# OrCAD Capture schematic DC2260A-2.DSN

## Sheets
1 1) TITLE: title: isoSPI 12-CELL BATTERY-STACK MONITOR; rev: 1; company: TM
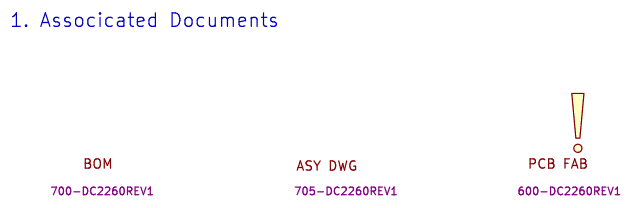
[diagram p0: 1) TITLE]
2 LTC6811IG-2: size Custom; rev: 2
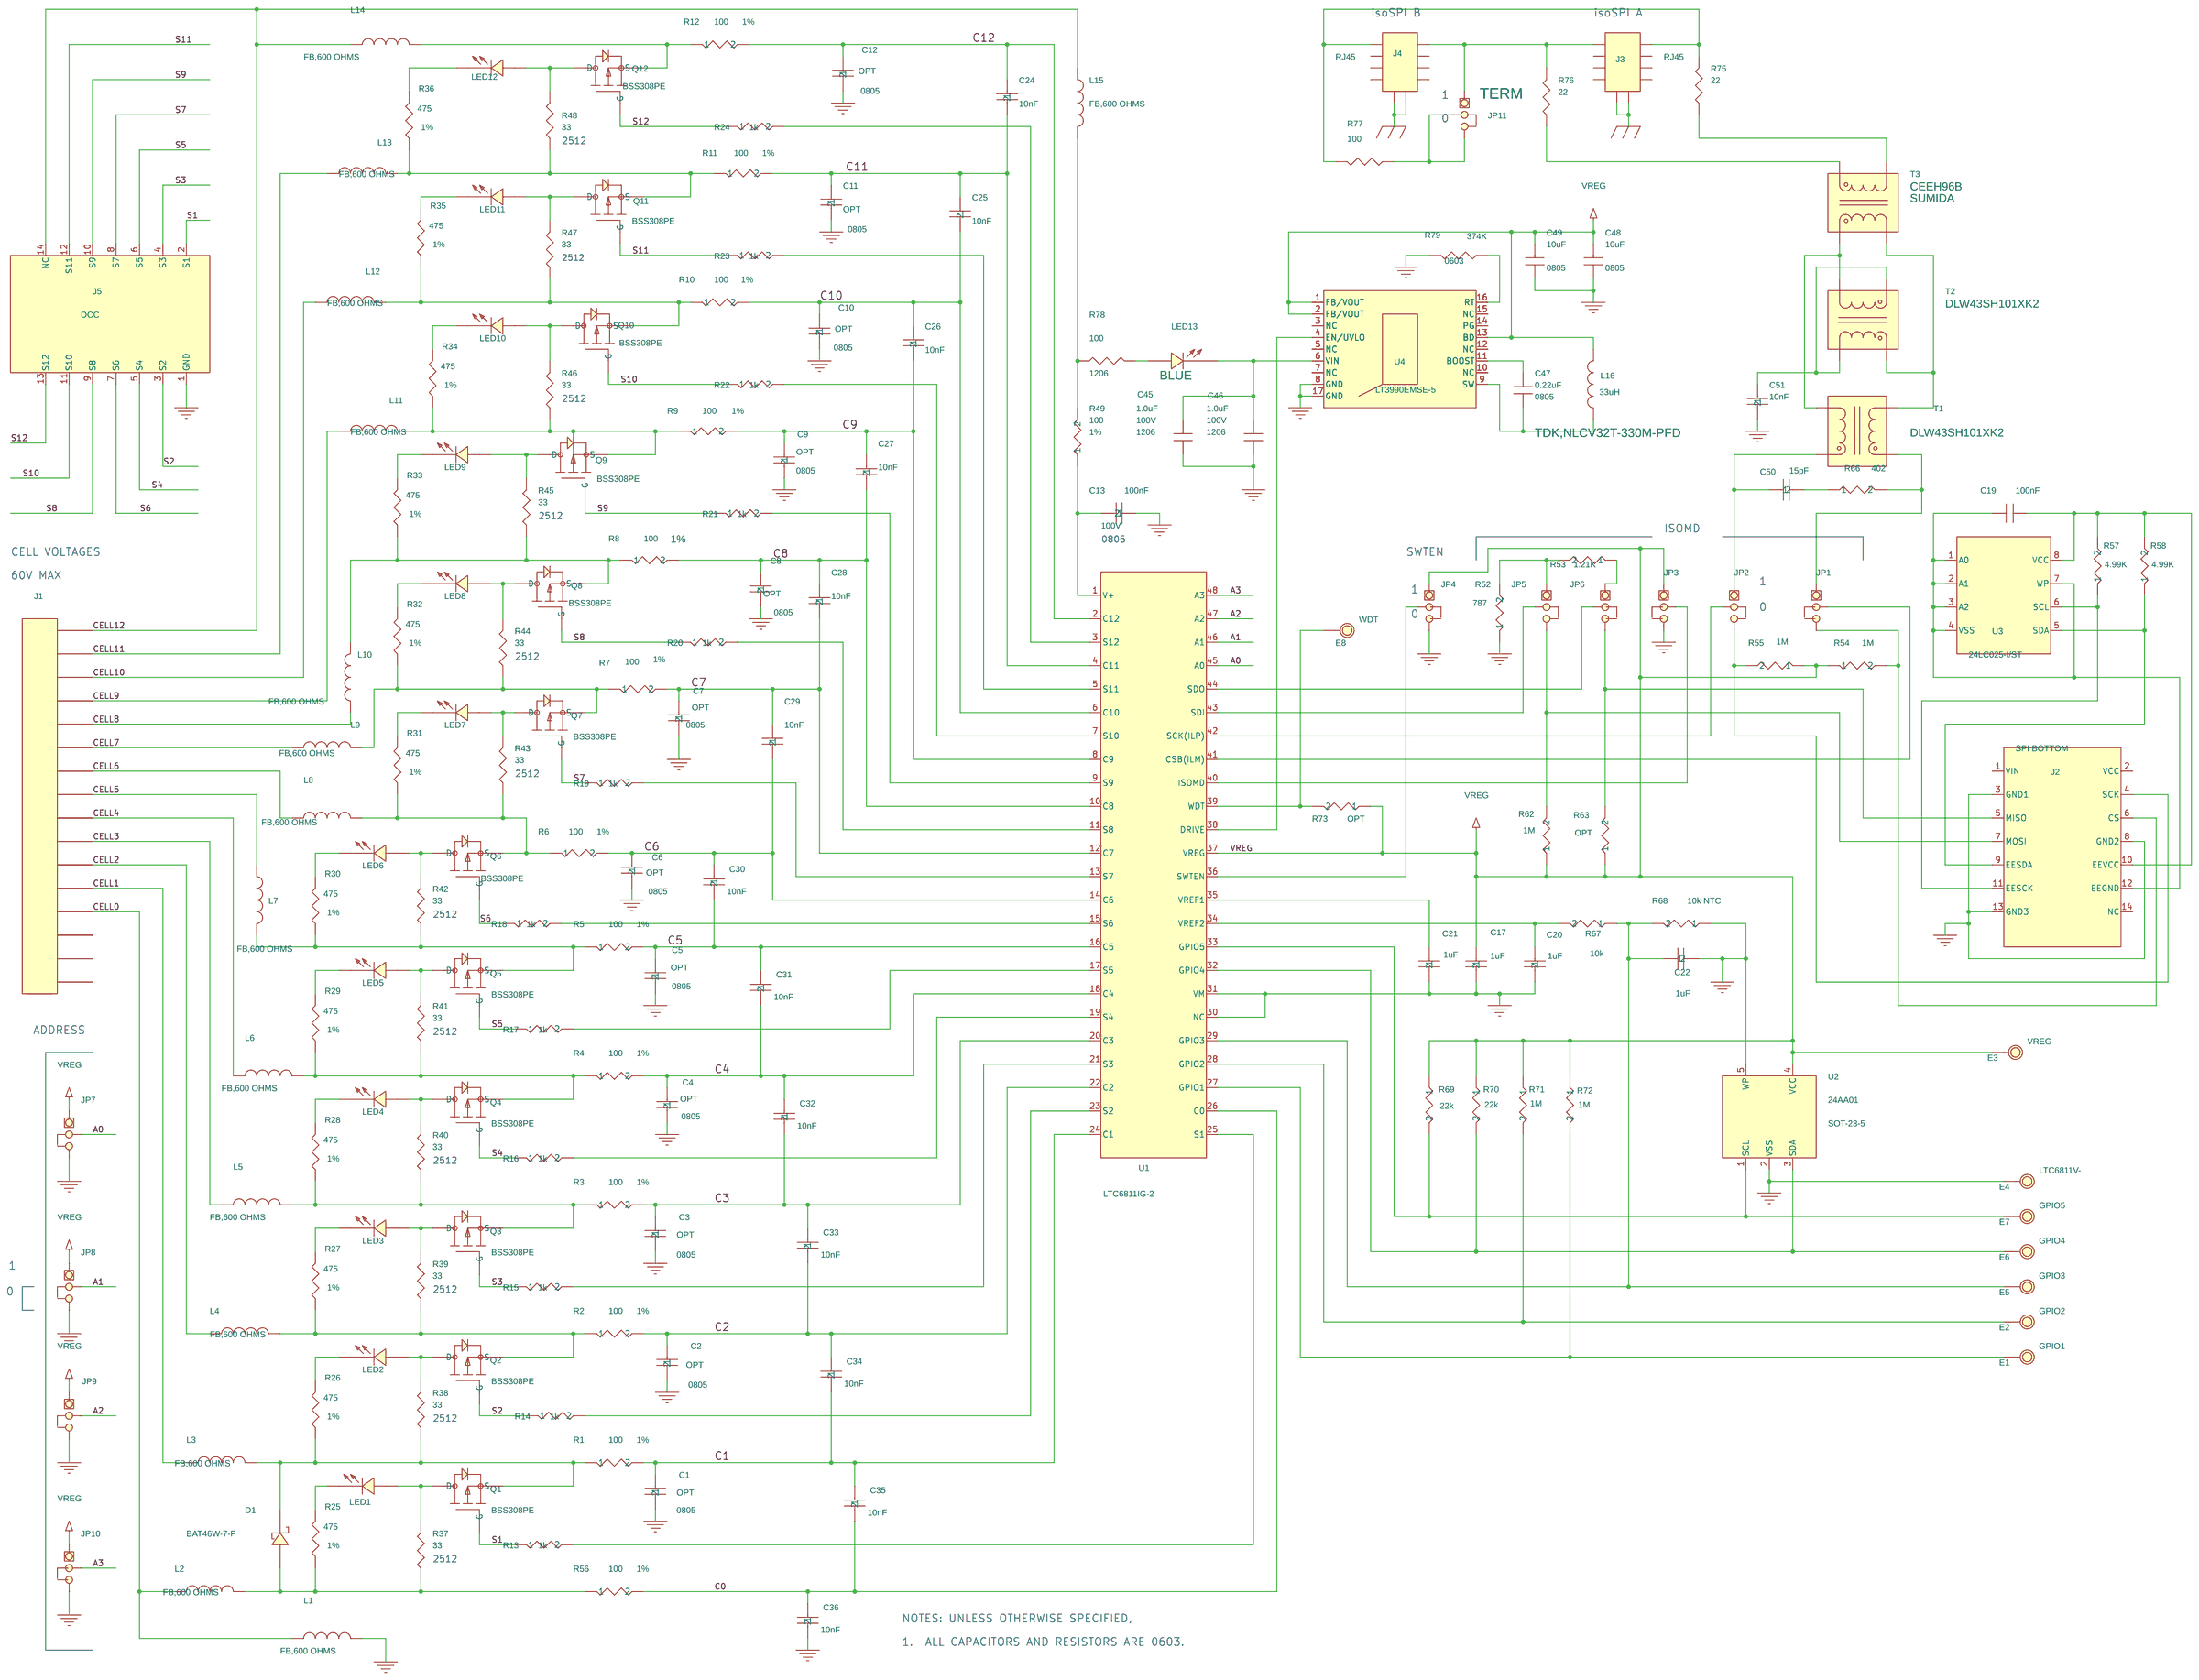
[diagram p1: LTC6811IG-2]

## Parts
sheet 1) TITLE
WARNINGL1  CALLOUT_BOM
WARNINGL2  CALLOUT_ASSY_DWG
WARNINGL3  CALLOUT_PCB_FAB
sheet LTC6811IG-2
C1  OPT  [0805]
C2  OPT  [0805]
C3  OPT  [0805]
C4  OPT  [0805]
C5  OPT  [0805]
C6  OPT  [0805]
C7  OPT  [0805]
C8  OPT  [0805]
C9  OPT  [0805]
C10  OPT  [0805]
C11  OPT  [0805]
C12  OPT  [0805]
C13  100nF  [C0805]
C17  1uF  [C0603]
C19  100nF  [C0603]
C20  1uF  [C0603]
C21  1uF  [C0603]
C22  1uF  [C0603]
C24  10nF  [C0603]
C25  10nF  [C0603]
C26  10nF  [C0603]
C27  10nF  [C0603]
C28  10nF  [C0603]
C29  10nF  [C0603]
C30  10nF  [C0603]
C31  10nF  [C0603]
C32  10nF  [C0603]
C33  10nF  [C0603]
C34  10nF  [C0603]
C35  10nF  [C0603]
C36  10nF  [C0603]
C45  1.0uF  [1206]
C46  1.0uF  [1206]
C47  0.22uF  [0805]
C48  10uF  [0805]
C49  10uF  [0805]
C50  15pF  [C0603]
C51  10nF  [C0603]
D1  BAT46W-7-F  [SOD123]
E1  GPIO1  [MILLMAX-2308-2]
E2  GPIO2  [MILLMAX-2308-2]
E3  VREG  [MILLMAX-2308-2]
E4  LTC6811V-  [MILLMAX-2308-2]
E5  GPIO3  [MILLMAX-2308-2]
E6  GPIO4  [MILLMAX-2308-2]
E7  GPIO5  [MILLMAX-2308-2]
E8  WDT  [MILLMAX-2308-2]
J1  HEADER 16  [CONN\WDMLLR\176168200]
J2  SPI BOTTOM  [HD2X7-079-MOLEX]
J3  RJ45  [RJ45]
J4  RJ45  [RJ45]
J5  DCC  [HD2X7-079-MOLEX]
JP1  JMP1X3  [JUMPER3\2MM]
JP2  JMP1X3  [JUMPER3\2MM]
JP3  JMP1X3  [JUMPER3\2MM]
JP4  JMP1X3  [JUMPER3\2MM]
JP5  JMP1X3  [JUMPER3\2MM]
JP6  JMP1X3  [JUMPER3\2MM]
JP7  JMP1X3  [JUMPER3\2MM]
JP8  JMP1X3  [JUMPER3\2MM]
JP9  JMP1X3  [JUMPER3\2MM]
JP10  JMP1X3  [JUMPER3\2MM]
JP11  JMP1X3  [JUMPER3\2MM]
L1  FB,600 OHMS  [1206]
L2  FB,600 OHMS  [1206]
L3  FB,600 OHMS  [1206]
L4  FB,600 OHMS  [1206]
L5  FB,600 OHMS  [1206]
L6  FB,600 OHMS  [1206]
L7  FB,600 OHMS  [1206]
L8  FB,600 OHMS  [1206]
L9  FB,600 OHMS  [1206]
L10  FB,600 OHMS  [1206]
L11  FB,600 OHMS  [1206]
L12  FB,600 OHMS  [1206]
L13  FB,600 OHMS  [1206]
L14  FB,600 OHMS  [1206]
L15  FB,600 OHMS  [1206]
L16  33uH  [IND-NLCV]
LED1  LED  [LED\LTST-C190KGKT]
LED2  LED  [LED\LTST-C190KGKT]
LED3  LED  [LED\LTST-C190KGKT]
LED4  LED  [LED\LTST-C190KGKT]
LED5  LED  [LED\LTST-C190KGKT]
LED6  LED  [LED\LTST-C190KGKT]
LED7  LED  [LED\LTST-C190KGKT]
LED8  LED  [LED\LTST-C190KGKT]
LED9  LED  [LED\LTST-C190KGKT]
LED10  LED  [LED\LTST-C190KGKT]
LED11  LED  [LED\LTST-C190KGKT]
LED12  LED  [LED\LTST-C190KGKT]
LED13  BLUE  [LED\LTST-C190KGKT]
P1  HEADER 16/SM
Q1  BSS308PE  [SOT23]
Q2  BSS308PE  [SOT23]
Q3  BSS308PE  [SOT23]
Q4  BSS308PE  [SOT23]
Q5  BSS308PE  [SOT23]
Q6  BSS308PE  [SOT23]
Q7  BSS308PE  [SOT23]
Q8  BSS308PE  [SOT23]
Q9  BSS308PE  [SOT23]
Q10  BSS308PE  [SOT23]
Q11  BSS308PE  [SOT23]
Q12  BSS308PE  [SOT23]
R1  100  [R0603]
R2  100  [R0603]
R3  100  [R0603]
R4  100  [R0603]
R5  100  [R0603]
R6  100  [R0603]
R7  100  [R0603]
R8  100  [R0603]
R9  100  [R0603]
R10  100  [R0603]
R11  100  [R0603]
R12  100  [R0603]
R13  1k  [R0603]
R14  1k  [R0603]
R15  1k  [R0603]
R16  1k  [R0603]
R17  1k  [R0603]
R18  1k  [R0603]
R19  1k  [R0603]
R20  1k  [R0603]
R21  1k  [R0603]
R22  1k  [R0603]
R23  1k  [R0603]
R24  1k  [R0603]
R25  475  [R0603]
R26  475  [R0603]
R27  475  [R0603]
R28  475  [R0603]
R29  475  [R0603]
R30  475  [R0603]
R31  475  [R0603]
R32  475  [R0603]
R33  475  [R0603]
R34  475  [R0603]
R35  475  [R0603]
R36  475  [R0603]
R37  33  [2512]
R38  33  [2512]
R39  33  [2512]
R40  33  [2512]
R41  33  [2512]
R42  33  [2512]
R43  33  [2512]
R44  33  [2512]
R45  33  [2512]
R46  33  [2512]
R47  33  [2512]
R48  33  [2512]
R49  100  [R0603]
R52  787  [R0603]
R53  1.21K  [R0603]
R54  1M  [0603]
R55  1M  [0603]
R56  100  [R0603]
R57  4.99K  [R0603]
R58  4.99K  [R0603]
R62  1M  [0603]
R63  OPT  [0603]
R66  402  [R0603]
R67  10k  [0603]
R68  10k NTC  [0603]
R69  22k  [0603]
R70  22k  [0603]
R71  1M  [0603]
R72  1M  [0603]
R73  OPT  [0603]
R75  22  [R0603]
R76  22  [R0603]
R77  100  [R0603]
R78  100  [1206]
R79  374K  [0603]
T1  DLW43SH101XK2  [TRANS-DLW43S]
T2  DLW43SH101XK2  [TRANS-DLW43S]
T3  CEEH96B  [TRANS-CEEH96B]
U1  LTC6811IG-2  [LTC-SSOP48-5.3MM]
U2  24AA01  [SOT-23-5]
U3  24LC025-I/ST  [ST-4.4MMTSSOP]
U4  LT3990EMSE-5  [MSE-16PIN]
XJP8  2mm Ctrs.
XJP9  2mm Ctrs.
XJP10  2mm Ctrs.
XJP11  2mm Ctrs.
XJP12  2mm Ctrs.
XJP13  2mm Ctrs.
XJP14  2mm Ctrs.
XJP15  2mm Ctrs.
XJP16  2mm Ctrs.
XJP17  2mm Ctrs.
XJP18  2mm Ctrs.

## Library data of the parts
WARNINGL1 = CALLOUT_BOM: Part Number: 700-DC2260REV1
WARNINGL2 = CALLOUT_ASSY_DWG: Part Number: 705-DC2260REV1
WARNINGL3 = CALLOUT_PCB_FAB: Part Number: 600-DC2260REV1
C1 = CAP_NP_1_16: CAP, 0603 100nF 10% 25V X7R; Part Number: MURATA GCM188R71E104KA57D
C2 = CAP_NP_1_15: CAP, 0603 100nF 10% 25V X7R; Part Number: MURATA GCM188R71E104KA57D
C3 = CAP_NP_1_13: CAP, 0603 100nF 10% 25V X7R; Part Number: MURATA GCM188R71E104KA57D
C4 = CAP_NP_1_10: CAP, 0603 100nF 10% 25V X7R; Part Number: MURATA GCM188R71E104KA57D
C5 = CAP_NP_1_24: CAP, 0603 100nF 10% 25V X7R; Part Number: MURATA GCM188R71E104KA57D
C6 = CAP_NP_1_29: CAP, 0603 100nF 10% 25V X7R; Part Number: MURATA GCM188R71E104KA57D
C7 = CAP_NP_1_6: CAP, 0603 100nF 10% 25V X7R; Part Number: MURATA GCM188R71E104KA57D
C8 = CAP_NP_1_3: CAP, 0603 100nF 10% 25V X7R; Part Number: MURATA GCM188R71E104KA57D
C9 = CAP_NP_1_27: CAP, 0603 100nF 10% 25V X7R; Part Number: MURATA GCM188R71E104KA57D
C10 = CAP_NP_1_28: CAP, 0603 100nF 10% 25V X7R; Part Number: MURATA GCM188R71E104KA57D
C11 = CAP_NP_1_8: CAP, 0603 100nF 10% 25V X7R; Part Number: MURATA GCM188R71E104KA57D
C12 = CAP_NP_1_9: CAP, 0603 100nF 10% 25V X7R; Part Number: MURATA GCM188R71E104KA57D
C13 = CAP_NP_1_11: CAP, 0805 100nF 20% 100V X7R; Part Number: MURATA GCM21BR72A104KA37; voltage: 100V
C17 = CAP_NP_1_30: CAP, 0603 100nF 10% 25V X7R; Part Number: MURATA GCM188R71E104KA57D
C19 = CAP0603: CAP, 0603 100nF 10% 25V X7R; Part Number: MURATA GCM188R71E104KA57D; Voltage: 25V
C20 = CAP_NP_1_21: CAP, 0603 100nF 10% 25V X7R; Part Number: MURATA GCM188R71E104KA57D
C21 = CAP_NP_1_18: CAP, 0603 100nF 10% 25V X7R; Part Number: MURATA GCM188R71E104KA57D
C22 = CAP_NP_1_22: CAP, 0603 100nF 10% 25V X7R; Part Number: MURATA GCM188R71E104KA57D
C24 = CAP_NP_1_26: CAP, 0603 100nF 10% 25V X7R; Part Number: MURATA GCM188R71E104KA57D
C25 = CAP_NP_1_23: CAP, 0603 100nF 10% 25V X7R; Part Number: MURATA GCM188R71E104KA57D
C26 = CAP_NP_1_17: CAP, 0603 100nF 10% 25V X7R; Part Number: MURATA GCM188R71E104KA57D
C27 = CAP_NP_1_12: CAP, 0603 100nF 10% 25V X7R; Part Number: MURATA GCM188R71E104KA57D
C28 = CAP_NP_1_2: CAP, 0603 100nF 10% 25V X7R; Part Number: MURATA GCM188R71E104KA57D
C29 = CAP_NP_1_5: CAP, 0603 100nF 10% 25V X7R; Part Number: MURATA GCM188R71E104KA57D
C30 = CAP_NP_1_4: CAP, 0603 100nF 10% 25V X7R; Part Number: MURATA GCM188R71E104KA57D
C31 = CAP_NP_1_31: CAP, 0603 100nF 10% 25V X7R; Part Number: MURATA GCM188R71E104KA57D
C32 = CAP_NP_1_19: CAP, 0603 100nF 10% 25V X7R; Part Number: MURATA GCM188R71E104KA57D
C33 = CAP_NP_1_20: CAP, 0603 100nF 10% 25V X7R; Part Number: MURATA GCM188R71E104KA57D
C34 = CAP_NP_1_25: CAP, 0603 100nF 10% 25V X7R; Part Number: MURATA GCM188R71E104KA57D
C35 = CAP_NP_1: CAP, 0603 100nF 10% 25V X7R; Part Number: MURATA GCM188R71E104KA57D
C36 = CAP_NP_1_14: CAP, 0603 100nF 10% 25V X7R; Part Number: MURATA GCM188R71E104KA57D
C45 C46 = 1.0uF_25V_10%_X7R_0805: CAP., 1uF, X7R, 100V, 10%, 0805; Voltage: 100V
C47 = 0.22uF_25V_10%_X7R_0805
C48 C49 = 10uF_10V_20%_X5R_0805
C50 = CAP_NP_1_7: CAP, 0603 100nF 10% 25V X7R; Part Number: MURATA GCM188R71E104KA57D
C51 = CAP_NP_1_1: CAP, 0603 100nF 10% 25V X7R; Part Number: MURATA GCM188R71E104KA57D
D1 = DIODE_SCHOTTKY
E1-E8 = CON_KEY_575-4: 5th Part Field: 3V to 3.6V
J1 = HEADER_16_1: HEADER, 1X16 3.5mm, HORIZ.; Part Number: WEIDMULLER 1761682001
J2 = HEADER_7X2_8
J3 = HEADER_16_8
J4 = HEADER_16_7
J5 = HEADER_7X2_9
JP1 = JMP1X3_1: HEADER,3PIN, 2mm; Part Number: SAMTEC TMM-103-02-L-S
JP2-JP10 = JMP1X3_2: HEADER,3PIN, 2mm; Part Number: SAMTEC TMM-103-02-L-S
JP11 = JMP1X3_2: HEADER,3PIN, 2mm; 1: TERM; Part Number: SAMTEC TMM-103-02-L-S
L1-L15 = FERRITE_BEAD,_33_OHM,_1206
L16 = INDUCTOR,_22uH,_TDK: Part Number: TDK,NLCV32T-330M-PFD
LED1-LED13 = LED_2: LED, 0603 GREEN; Part Number: LITE-ON LTST-C190KGKT
P1 = HEADER_16_SM_9: CONN. MATING 1X16 3.5 HORZ; Part Number: WEIDMULLER 1615770000
Q1-Q12 = Si2311DS_0: XSTR, MOSFET, P-CHANNEL; Part Number: RENASAS RQJ0303PGDQALT
R1 = R_40: RES, 0603 100 OHMS 1% 1/10W; Part Number: NIC NRC06F1000TRF; Tol: 1%
R2 = R_39: RES, 0603 100 OHMS 1% 1/10W; Part Number: NIC NRC06F1000TRF; Tol: 1%
R3 = R_38: RES, 0603 100 OHMS 1% 1/10W; Part Number: NIC NRC06F1000TRF; Tol: 1%
R4 = R_37: RES, 0603 100 OHMS 1% 1/10W; Part Number: NIC NRC06F1000TRF; Tol: 1%
R5 = R_20: RES, 0603 100 OHMS 1% 1/10W; Part Number: NIC NRC06F1000TRF; Tol: 1%
R6 = R_25: RES, 0603 100 OHMS 1% 1/10W; Part Number: NIC NRC06F1000TRF; Tol: 1%
R7 = R_33: RES, 0603 100 OHMS 1% 1/10W; Part Number: NIC NRC06F1000TRF; Tol: 1%
R8 = R_32: RES, 0603 100 OHMS 1% 1/10W; Part Number: NIC NRC06F1000TRF; Tol: 1%
R9 = R_23: RES, 0603 100 OHMS 1% 1/10W; Part Number: NIC NRC06F1000TRF; Tol: 1%
R10 = R_24: RES, 0603 100 OHMS 1% 1/10W; Part Number: NIC NRC06F1000TRF; Tol: 1%
R11 = R_36: RES, 0603 100 OHMS 1% 1/10W; Part Number: NIC NRC06F1000TRF; Tol: 1%
R12 = R_35: RES, 0603 100 OHMS 1% 1/10W; Part Number: NIC NRC06F1000TRF; Tol: 1%
R13 = R_9: RES, 0603 3.3k OHMS 5% 1/10W; Part Number: NIC NRC06J332TRF; Tol: 5%
R14 = R_6: RES, 0603 3.3k OHMS 5% 1/10W; Part Number: NIC NRC06J332TRF; Tol: 5%
R15 = R_4: RES, 0603 3.3k OHMS 5% 1/10W; Part Number: NIC NRC06J332TRF; Tol: 5%
R16 = R_41: RES, 0603 3.3k OHMS 5% 1/10W; Part Number: NIC NRC06J332TRF; Tol: 5%
R17 = R_2: RES, 0603 3.3k OHMS 5% 1/10W; Part Number: NIC NRC06J332TRF; Tol: 5%
R18 = R_18: RES, 0603 3.3k OHMS 5% 1/10W; Part Number: NIC NRC06J332TRF; Tol: 5%
R19 = R_28: RES, 0603 3.3k OHMS 5% 1/10W; Part Number: NIC NRC06J332TRF; Tol: 5%
R20 = R_27: RES, 0603 3.3k OHMS 5% 1/10W; Part Number: NIC NRC06J332TRF; Tol: 5%
R21 = R_15: RES, 0603 3.3k OHMS 5% 1/10W; Part Number: NIC NRC06J332TRF; Tol: 5%
R22 = R_16: RES, 0603 3.3k OHMS 5% 1/10W; Part Number: NIC NRC06J332TRF; Tol: 5%
R23 = R_30: RES, 0603 3.3k OHMS 5% 1/10W; Part Number: NIC NRC06J332TRF; Tol: 5%; Tolerance: 5%
R24 = R_13: RES, 0603 3.3k OHMS 5% 1/10W; Part Number: NIC NRC06J332TRF; Tol: 5%; Tolerance: 5%
R25-R36 R75-R77 R79 = AAC-0603: RES, 0603 475 OHMS 1% 1/10W; Part Number: NIC NRC06F4750TRF; Tol: 1%
R37-R48 = AAC-0603: RES, 2512 33 OHMS 5% 1W; Part Number: NIC NRC100J330TRF; Tolerance: 5%
R49 = R_12: RES, 0603 100 OHMS 1% 1/10W; Part Number: NIC NRC06F1000TRF; Tol: 1%
R52 = R_29: RES, 0603 100 OHMS 1% 1/10W; Part Number: NIC NRC06F1000TRF; Tol: 1%
R53 = R_1: RES, 0603 100 OHMS 1% 1/10W; Part Number: NIC NRC06F1000TRF; Tol: 1%
R54 = R_22: RES, 0603 100 OHMS 1% 1/10W; Part Number: NIC NRC06F1000TRF; Tol: 1%
R55 = R_7: RES, 0603 100 OHMS 1% 1/10W; Part Number: NIC NRC06F1000TRF; Tol: 1%
R56 = R_3: RES, 0603 100 OHMS 1% 1/10W; Part Number: NIC NRC06F1000TRF; Tol: 1%
R57 = R_34: RES, 0603 100 OHMS 1% 1/10W; Part Number: NIC NRC06F1000TRF; Tol: 1%
R58 = R_5: RES, 0603 100 OHMS 1% 1/10W; Part Number: NIC NRC06F1000TRF; Tol: 1%
R62 = R_21: RES, 0603 4.99K OHMS  1% 1/10W; 5%: 1%; Part Number: NIC NRC06F4991TRF; Tol: 1%
R63 = R_26: RES, 0603 4.99K OHMS  1% 1/10W; 5%: 1%; Part Number: NIC NRC06F4991TRF; Tol: 1%
R66 = R: RES, 0603 100 OHMS 1% 1/10W; Part Number: NIC NRC06F1000TRF; Tol: 1%
R67 = R_10: RES, 0603 4.99K OHMS  1% 1/10W; 5%: 1%; Part Number: NIC NRC06F4991TRF; Tol: 1%
R68 = R_31: RES, 0603 4.99K OHMS  1% 1/10W; 5%: 1%; Part Number: NIC NRC06F4991TRF; Tol: 1%
R69 = R_17: RES, 0603 4.99K OHMS  1% 1/10W; 5%: 1%; Part Number: NIC NRC06F4991TRF; Tol: 1%
R70 = R_8: RES, 0603 4.99K OHMS  1% 1/10W; 5%: 1%; Part Number: NIC NRC06F4991TRF; Tol: 1%
R71 = R_19: RES, 0603 4.99K OHMS  1% 1/10W; 5%: 1%; Part Number: NIC NRC06F4991TRF; Tol: 1%
R72 = R_14: RES, 0603 4.99K OHMS  1% 1/10W; 5%: 1%; Part Number: NIC NRC06F4991TRF; Tol: 1%
R73 = R_11: RES, 0603 4.99K OHMS  1% 1/10W; 5%: 1%; Part Number: NIC NRC06F4991TRF; Tol: 1%
R78 = 0_OHM_JUMPER_1_8W_0805
T1 T2 = TRANS-PA0950_22: 4TH PART FIELD: PULSE,; 5TH PART FIELD: PA08xx; 7TH PART FIELD: TRANS.,
T3 = TRANS-PA0950_10: 4TH PART FIELD: SUMIDA; 5TH PART FIELD: PA08xx; 7TH PART FIELD: TRANS.,
U1 = IC_CNX_RM009_13: IC, BATTERY MONITOR; Part Number: LINEAR TECH. LTC6803IG-4
U2 = 24LC025_1: IC, 24LC025-I/ST; Part Number: MICROCHIP TECH. 24LC025-I/ST
U3 = 24LC025_0: IC, 24LC025-I/ST; Part Number: MICROCHIP TECH. 24LC025-I/ST
U4 = LT3990EMSE-5_2
XJP8-XJP18 = Samtec_2SN-BK-G_1

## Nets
GND: C1.2 C2.2 C3.2 C4.2 C5.2 C6.2 C7.2 C8.2 C9.2 C10.2 C11.2 C12.2 C13.1 C17.2 C20.2 C21.2 C22.2 C36.2 C45.2 C46.2 C48.2 C49.2 C51.2 E4.1 J2.3(GND1) J2.8(GND2) J2.13(GND3) J5.1(GND) JP3.3 JP4.3 JP7.3 JP8.3 JP9.3 JP10.3 L1.2 R52.1 R68.1 R79.2 U1.30(NC) U1.31(VM) U2.2(VSS) U2.5(WP) U4.8(GND) U4.17(GND)
GND_EARTH: J3.11 J3.12 J4.11 J4.12
A0: JP7.2 U1.45(A0)
A1: JP8.2 U1.46(A1)
A2: JP9.2 U1.47(A2)
A3: JP10.2 U1.48(A3)
C0: C35.2 C36.1 R56.2 U1.26(C0)
C1: C1.1 C34.2 C35.1 R1.2 U1.24(C1)
C2: C2.1 C33.2 C34.1 R2.2 U1.22(C2)
C3: C3.1 C32.2 C33.1 R3.2 U1.20(C3)
C4: C4.1 C31.2 C32.1 R4.2 U1.18(C4)
C5: C5.1 C30.2 C31.1 R5.2 U1.16(C5)
C6: C6.1 C29.2 C30.1 R6.2 U1.14(C6)
C7: C7.1 C28.2 C29.1 R7.2 U1.12(C7)
C8: C8.1 C27.2 C28.1 R8.2 U1.10(C8)
C9: C9.1 C26.2 C27.1 R9.2 U1.8(C9)
C10: C10.1 C25.2 C26.1 R10.2 U1.6(C10)
C11: C11.1 C24.2 C25.1 R11.2 U1.4(C11)
C12: C12.1 C24.1 R12.2 U1.2(C12)
CELL0: J1.4 L1.1 L2.1
CELL1: J1.5 L3.1
CELL2: J1.6 L4.1
CELL3: J1.7 L5.1
CELL4: J1.8 L6.1
CELL5: J1.9 L7.1
CELL6: J1.10 L8.1
CELL7: J1.11 L9.1
CELL8: J1.12 L10.1
CELL9: J1.13 L11.1
CELL10: J1.14 L12.1
CELL11: J1.15 L13.1
CELL12: J1.16 J5.14(NC) L14.1 L15.2
S1: J5.2(S1) Q1.1(G) R13.1
S2: J5.3(S2) Q2.1(G) R14.1
S3: J5.4(S3) Q3.1(G) R15.1
S4: J5.5(S4) Q4.1(G) R16.1
S5: J5.6(S5) Q5.1(G) R17.1
S6: J5.7(S6) Q6.1(G) R18.1
S7: J5.8(S7) Q7.1(G) R19.1
S8: J5.9(S8) Q8.1(G) R20.1
S9: J5.10(S9) Q9.1(G) R21.1
S10: J5.11(S10) Q10.1(G) R22.1
S11: J5.12(S11) Q11.1(G) R23.1
S12: J5.13(S12) Q12.1(G) R24.1
VREG: C17.1 C48.1 C49.1 E3.1 JP3.1 JP4.1 JP7.1 JP8.1 JP9.1 JP10.1 L16.2 R54.1 R55.1 R62.1 R63.1 R69.1 R70.1 R71.1 R72.1 R73.1 U1.37(VREG) U2.4(VCC) U4.1(FB/VOUT) U4.2(FB/VOUT) U4.13(BD)
N16894792: L12.2 Q10.2(S) R10.1 R35.1 R47.1
N16896684: R15.2 U1.21(S3)
N16899008: R22.2 U1.7(S10)
N16899273: R21.2 U1.9(S9)
N16900373: R17.2 U1.17(S5)
N16900491: R16.2 U1.19(S4)
N17077012: L13.2 Q11.2(S) R11.1 R36.1 R48.1
N17214407: LED9.2(ANODE) Q9.3(D) R45.2
N17299634: L10.2 Q8.2(S) R8.1 R33.1 R45.1
N17302459: LED8.2(ANODE) Q8.3(D) R44.2
N17327723: L9.2 Q7.2(S) R7.1 R32.1 R44.1
N17391540: L7.2 Q5.2(S) R5.1 R30.1 R42.1
N17392236: L8.2 Q6.2(S) R6.1 R31.1 R43.1
N17459739: L6.2 Q4.2(S) R4.1 R29.1 R41.1
N17477747: L4.2 Q2.2(S) R2.1 R27.1 R39.1
N17479843: D1.2(CATHODE) L3.2 Q1.2(S) R1.1 R26.1 R38.1
N17513285: L5.2 Q3.2(S) R3.1 R28.1 R40.1
N17555838: LED2.2(ANODE) Q2.3(D) R38.2
N18079873: L11.2 Q9.2(S) R9.1 R34.1 R46.1
N18585560: LED12.2(ANODE) Q12.3(D) R48.2
N18595274: L14.2 Q12.2(S) R12.1
N18610156: LED11.2(ANODE) Q11.3(D) R47.2
N18624594: LED10.2(ANODE) Q10.3(D) R46.2
N18772000: LED4.2(ANODE) Q4.3(D) R40.2
N18793447: LED3.2(ANODE) Q3.3(D) R39.2
N18852330: LED1.2(ANODE) Q1.3(D) R37.2
N20402864: JP2.2 U1.42(SCK(ILP))
N21906162: C13.2 R49.1 U1.1(V+)
N22556835: LED12.1(CATHODE) R36.2
N22563264: LED11.1(CATHODE) R35.2
N22585558: LED10.1(CATHODE) R34.2
N22602851: LED8.1(CATHODE) R32.2
N22608274: LED7.2(ANODE) Q7.3(D) R43.2
N22628857: LED7.1(CATHODE) R31.2
N22647294: LED6.1(CATHODE) R30.2
N22654996: LED5.2(ANODE) Q5.3(D) R41.2
N22657124: LED5.1(CATHODE) R29.2
N22667803: LED4.1(CATHODE) R28.2
N22678339: LED3.1(CATHODE) R27.2
N22688557: LED2.1(CATHODE) R26.2
N22696923: LED1.1(CATHODE) R25.2
N22698314: D1.1(ANODE) L2.2 R25.1 R37.1 R56.1
N23186394: R24.2 U1.3(S12)
N23211330: R23.2 U1.5(S11)
N23706215: LED6.2(ANODE) Q6.3(D) R42.2
N23999597: R20.2 U1.11(S8)
N24165322: U1.38(DRIVE) U4.4(EN/UVLO)
N24191860: E8.1 R73.2 U1.39(WDT)
N24205217: C19.1 J2.12(EEGND) U3.1(A0) U3.2(A1) U3.3(A2) U3.4(VSS) U3.7(WP)
N24210843: C19.2 J2.10(EEVCC) R57.2 R58.2 U3.8(VCC)
N24220606: J2.11(EESCK) R57.1 U3.6(SCL)
N24222804: J2.9(EESDA) R58.1 U3.5(SDA)
N24251056: J2.4(SCK) JP2.3 R55.2
N24253378: J2.6(CS) JP1.3 R54.2
N24276187: J2.5(MISO) JP6.3 R63.2
N24276780: J2.7(MOSI) JP5.3 R62.2
N24287460: C21.1 U1.35(VREF1)
N24296505: C20.1 R67.2 U1.34(VREF2)
N24305984: C22.1 E5.1 R67.1 R68.2 U1.29(GPIO3)
N24309016: E7.1 R69.2 U1.33(GPIO5) U2.1(SCL)
N24351642: R14.2 U1.23(S2)
N24356734: R13.2 U1.25(S1)
N24363783: E2.1 R71.2 U1.28(GPIO2)
N24376054: E1.1 R72.2 U1.27(GPIO1)
N24433774: E6.1 R70.2 U1.32(GPIO4) U2.3(SDA)
N24617740: R18.2 U1.15(S6)
N24916160: J3.1 J4.1 R75.2 R77.2
N25041413: JP6.2 U1.44(SDO)
N25041419: JP5.2 U1.43(SDI)
N25070181: R19.2 U1.13(S7)
N25154641: J3.2 J4.2 JP11.1 R76.2
N25808839: L15.1 R49.2 R78.1
N25811046: LED9.1(CATHODE) R33.2
N25824436: JP11.2 JP11.3 R77.1
N25829434: JP4.2 U1.36(SWTEN)
N25832397: JP1.2 U1.41(CSB(ILM))
N25833050: JP3.2 U1.40(ISOMD)
N25833538: JP6.1 R53.1
N25833710: JP5.1 R52.2 R53.2
N25838734: C45.1 C46.1 LED13.1(CATHODE) U4.6(VIN)
N25839024: C47.2 U4.11(BOOST)
N25839026: C47.1 L16.1 U4.9(SW)
N25839097: R79.1 U4.16(RT)
N25845022: LED13.2(ANODE) R78.2
N25866470: JP1.1 R66.2 T1.4
N25866547: C50.1 JP2.1 T1.1
N25869588: C50.2 R66.1
N25869617: R76.1 T3.2
N25869622: R75.1 T3.1
N25869626: T1.2 T2.2 T3.3
N25869701: T1.3 T2.4 T3.4
N25872550: C51.1 T2.1 T2.3

Not connected (* = marked no-connect by the designer): J1 1 2 3; J2 1(VIN) 2(VCC) 14(NC); J3 3 4 5 6 7 8; J4 3 4 5 6 7 8; U4 3(NC) 5(NC) 7(NC) 10(NC) 12(NC) 14(PG) 15(NC)

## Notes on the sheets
sheet 1
- 1. Associcated Documents
sheet 2
- isoSPI B
- isoSPI A
- 1
- 0
- 2512
- 2512
- 2512
- 2512
- ISOMD
- 0805
- CELL VOLTAGES
- SWTEN
- 60V MAX
- 1
- 1
- 0
- 0
- 2512
- 2512
- 2512
- ADDRESS
- 2512
- 2512
- 1
- 0
- 2512
- 2512
- 2512
- NOTES: UNLESS OTHERWISE SPECIFIED,
- 1.  ALL CAPACITORS AND RESISTORS ARE 0603.
